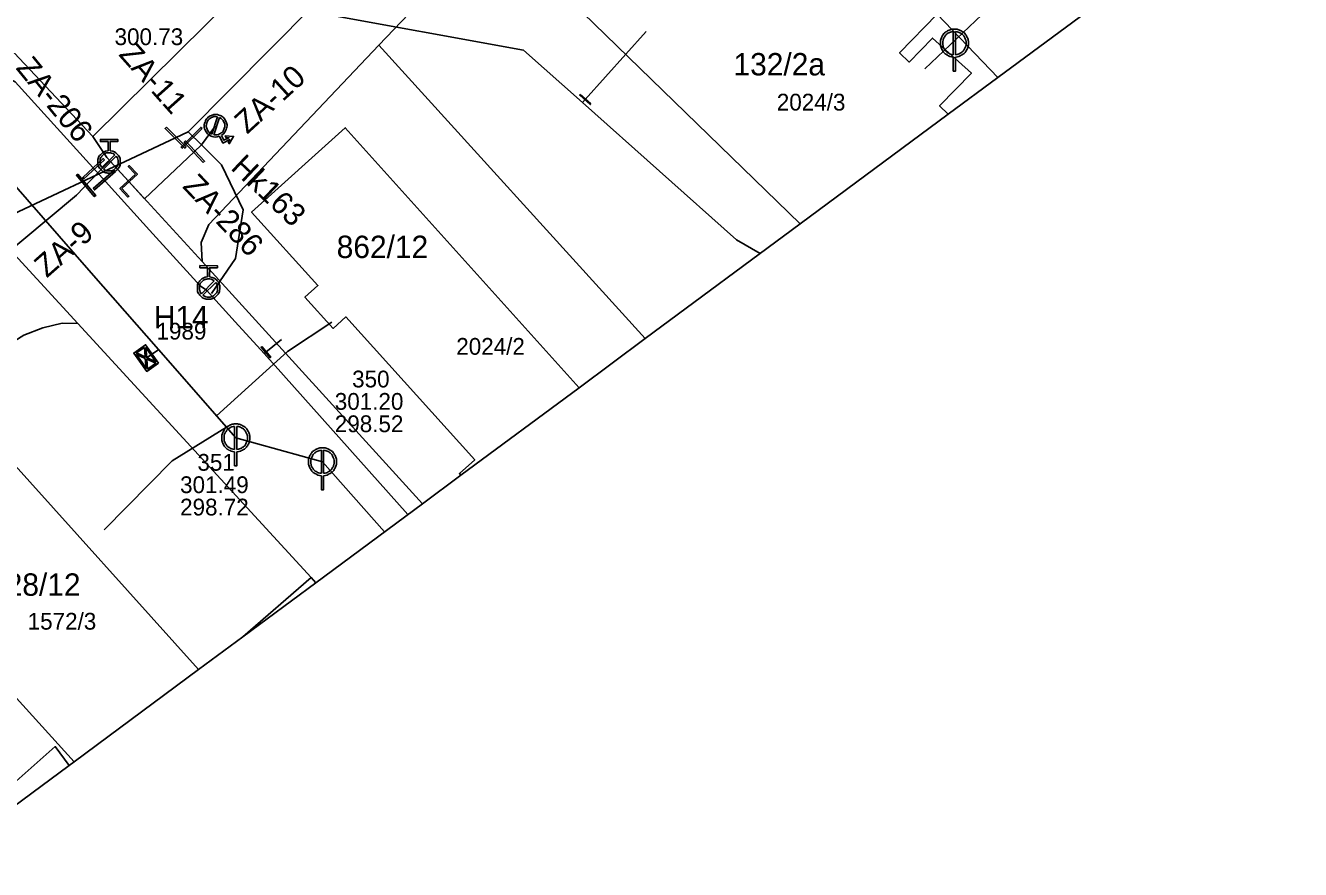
# Model space of a CAD drawing. Extents: x -570890 to -570546, y -1086481 to -1086296.
# Drawn here: x -570685 to -570571, y -1086481.2 to -1086405.7 of the extents above; entities that cross this region are included whole.
import ezdxf

# ---------------------------------------------------------------- set-up
doc = ezdxf.new("R2010")
doc.units = 0
for name, color, linetype in [('Adresní místo-text', 7, 'Continuous'), ('Armatura - popis', 7, 'Continuous'), ('Armatura vodovodní', 7, 'Continuous'), ('Default', 7, 'Continuous'), ('Dešťová vpusť', 7, 'Continuous'), ('Hydrant', 7, 'Continuous'), ('Kanalizační přípojka', 7, 'Continuous'), ('Kanalizační stoka', 7, 'Continuous'), ('Kanalizační šachta', 7, 'Continuous'), ('Označení hydrantu', 7, 'Continuous'), ('Parcela-polygon', 7, 'Continuous'), ('Parcela-text', 7, 'Continuous'), ('Popis šachty', 7, 'Continuous'), ('Vodovodní přípojka', 7, 'Continuous'), ('Vodovodní řad', 7, 'Continuous'), ('Změna materiálu', 7, 'Continuous')]:
    doc.layers.add(name, color=color, linetype=linetype)

msp = doc.modelspace()

# ---------------------------------------------------------------- linework, layer by layer
at = {"layer": 'Armatura vodovodní'}
for points in [[(-570635.43, -1086411.89), (-570634.49, -1086412.72), (-570634.54, -1086412.78), (-570635.48, -1086411.95), (-570635.43, -1086411.89)], [(-570672.44, -1086414.8), (-570670.67, -1086416.57), (-570670.78, -1086416.68), (-570672.55, -1086414.91), (-570672.44, -1086414.8)], [(-570669.25, -1086414.93), (-570671.02, -1086416.69), (-570671.13, -1086416.58), (-570669.36, -1086414.82), (-570669.25, -1086414.93)], [(-570669.14, -1086417.95), (-570670.86, -1086416.14), (-570670.74, -1086416.03), (-570669.02, -1086417.84), (-570669.14, -1086417.95)], [(-570677.98, -1086417.72), (-570679.81, -1086419.42), (-570679.91, -1086419.31), (-570678.08, -1086417.61), (-570677.98, -1086417.72)], [(-570680.36, -1086418.99), (-570678.76, -1086420.91), (-570678.88, -1086421.01), (-570680.48, -1086419.09), (-570680.36, -1086418.99)], [(-570677, -1086418.75), (-570678.87, -1086420.41), (-570678.98, -1086420.29), (-570677.1, -1086418.64), (-570677, -1086418.75)], [(-570663.91, -1086434.41), (-570663.11, -1086435.37), (-570663.17, -1086435.42), (-570663.97, -1086434.46), (-570663.91, -1086434.41)]]:
    msp.add_lwpolyline(points, dxfattribs=at)
at = {"layer": 'Default'}
for points in [[(-570602.08, -1086408.53), (-570602.34, -1086408.51), (-570602.6, -1086408.36), (-570602.9, -1086408.2), (-570603.07, -1086407.9), (-570603.23, -1086407.6), (-570603.23, -1086407.28), (-570603.23, -1086406.95), (-570603.06, -1086406.65), (-570602.89, -1086406.35), (-570602.6, -1086406.19), (-570602.3, -1086406.03), (-570601.98, -1086406.03), (-570601.67, -1086406.03), (-570601.37, -1086406.19), (-570601.07, -1086406.35), (-570600.9, -1086406.65), (-570600.73, -1086406.95), (-570600.73, -1086407.28), (-570600.73, -1086407.6), (-570600.89, -1086407.9), (-570601.06, -1086408.2), (-570601.36, -1086408.36), (-570601.62, -1086408.51), (-570601.88, -1086408.53)], [(-570602.08, -1086406.24), (-570602.28, -1086406.26), (-570602.5, -1086406.37), (-570602.74, -1086406.51), (-570602.88, -1086406.76), (-570603.02, -1086407.01), (-570603.02, -1086407.28), (-570603.02, -1086407.55), (-570602.89, -1086407.8), (-570602.75, -1086408.04), (-570602.5, -1086408.18), (-570602.29, -1086408.3), (-570602.08, -1086408.32)], [(-570601.88, -1086408.32), (-570601.67, -1086408.3), (-570601.46, -1086408.18), (-570601.21, -1086408.04), (-570601.07, -1086407.8), (-570600.94, -1086407.55), (-570600.94, -1086407.28), (-570600.94, -1086407.01), (-570601.08, -1086406.76), (-570601.22, -1086406.51), (-570601.47, -1086406.37), (-570601.68, -1086406.26), (-570601.88, -1086406.24)], [(-570667.69, -1086415.61), (-570668.01, -1086415.73), (-570668.35, -1086415.62), (-570668.74, -1086415.49), (-570668.93, -1086415.12), (-570669.12, -1086414.75), (-570668.99, -1086414.36), (-570668.88, -1086414.01), (-570668.57, -1086413.82)], [(-570667.88, -1086413.87), (-570668.15, -1086413.81), (-570668.41, -1086413.94), (-570668.71, -1086414.1), (-570668.81, -1086414.42), (-570668.92, -1086414.74), (-570668.76, -1086415.04), (-570668.63, -1086415.3), (-570668.38, -1086415.41)], [(-570668.41, -1086413.74), (-570668.07, -1086413.6), (-570667.73, -1086413.72), (-570667.33, -1086413.85), (-570667.15, -1086414.22), (-570666.96, -1086414.59), (-570667.09, -1086414.98), (-570667.2, -1086415.34), (-570667.52, -1086415.53)], [(-570668.2, -1086415.47), (-570667.93, -1086415.52), (-570667.67, -1086415.39), (-570667.37, -1086415.24), (-570667.27, -1086414.92), (-570667.16, -1086414.6), (-570667.32, -1086414.3), (-570667.45, -1086414.04), (-570667.7, -1086413.93)], [(-570677.47, -1086416.9), (-570677.11, -1086416.93), (-570676.85, -1086417.19), (-570676.56, -1086417.49), (-570676.56, -1086417.9), (-570676.56, -1086418.32), (-570676.85, -1086418.61), (-570677.15, -1086418.9), (-570677.56, -1086418.9), (-570677.97, -1086418.9), (-570678.27, -1086418.61), (-570678.56, -1086418.32), (-570678.56, -1086417.9), (-570678.56, -1086417.49), (-570678.27, -1086417.19), (-570678.01, -1086416.93), (-570677.65, -1086416.9)], [(-570677.05, -1086417.26), (-570677.27, -1086417.09), (-570677.56, -1086417.09), (-570677.9, -1086417.09), (-570678.14, -1086417.32), (-570678.37, -1086417.56), (-570678.37, -1086417.9), (-570678.37, -1086418.19), (-570678.2, -1086418.41)], [(-570678.07, -1086418.54), (-570677.85, -1086418.71), (-570677.56, -1086418.71), (-570677.23, -1086418.71), (-570676.99, -1086418.47), (-570676.75, -1086418.24), (-570676.75, -1086417.9), (-570676.75, -1086417.61), (-570676.92, -1086417.39)], [(-570668.57, -1086428.19), (-570668.21, -1086428.22), (-570667.95, -1086428.48), (-570667.66, -1086428.77), (-570667.67, -1086429.19), (-570667.67, -1086429.6), (-570667.96, -1086429.89), (-570668.26, -1086430.18), (-570668.67, -1086430.18), (-570669.08, -1086430.18), (-570669.38, -1086429.89), (-570669.67, -1086429.59), (-570669.67, -1086429.18), (-570669.66, -1086428.76), (-570669.37, -1086428.47), (-570669.11, -1086428.21), (-570668.76, -1086428.19)], [(-570668.16, -1086428.55), (-570668.37, -1086428.37), (-570668.66, -1086428.37), (-570669, -1086428.37), (-570669.24, -1086428.6), (-570669.48, -1086428.84), (-570669.48, -1086429.18), (-570669.48, -1086429.47), (-570669.31, -1086429.69)], [(-570669.17, -1086429.82), (-570668.96, -1086429.99), (-570668.67, -1086429.99), (-570668.34, -1086429.99), (-570668.1, -1086429.76), (-570667.86, -1086429.52), (-570667.86, -1086429.18), (-570667.85, -1086428.89), (-570668.03, -1086428.68)], [(-570666.34, -1086443.83), (-570666.59, -1086443.81), (-570666.86, -1086443.67), (-570667.15, -1086443.5), (-570667.32, -1086443.21), (-570667.48, -1086442.91), (-570667.48, -1086442.58), (-570667.48, -1086442.26), (-570667.31, -1086441.96), (-570667.15, -1086441.66), (-570666.85, -1086441.49), (-570666.55, -1086441.33), (-570666.23, -1086441.33), (-570665.92, -1086441.33), (-570665.62, -1086441.49), (-570665.32, -1086441.66), (-570665.15, -1086441.96), (-570664.98, -1086442.26), (-570664.98, -1086442.58), (-570664.98, -1086442.91), (-570665.15, -1086443.21), (-570665.31, -1086443.5), (-570665.61, -1086443.67), (-570665.87, -1086443.81), (-570666.13, -1086443.83)], [(-570666.34, -1086441.55), (-570666.53, -1086441.56), (-570666.75, -1086441.68), (-570667, -1086441.81), (-570667.14, -1086442.06), (-570667.28, -1086442.31), (-570667.28, -1086442.58), (-570667.28, -1086442.85), (-570667.14, -1086443.1), (-570667, -1086443.35), (-570666.75, -1086443.48), (-570666.54, -1086443.6), (-570666.34, -1086443.62)], [(-570666.13, -1086443.62), (-570665.93, -1086443.6), (-570665.71, -1086443.48), (-570665.46, -1086443.35), (-570665.33, -1086443.1), (-570665.19, -1086442.85), (-570665.19, -1086442.58), (-570665.19, -1086442.31), (-570665.33, -1086442.06), (-570665.47, -1086441.81), (-570665.72, -1086441.68), (-570665.93, -1086441.56), (-570666.13, -1086441.55)], [(-570658.58, -1086445.97), (-570658.84, -1086445.95), (-570659.1, -1086445.8), (-570659.4, -1086445.64), (-570659.56, -1086445.34), (-570659.73, -1086445.04), (-570659.73, -1086444.72), (-570659.73, -1086444.39), (-570659.56, -1086444.09), (-570659.39, -1086443.79), (-570659.09, -1086443.63), (-570658.8, -1086443.47), (-570658.48, -1086443.47), (-570658.16, -1086443.47), (-570657.87, -1086443.63), (-570657.57, -1086443.79), (-570657.4, -1086444.09), (-570657.23, -1086444.39), (-570657.23, -1086444.72), (-570657.23, -1086445.04), (-570657.39, -1086445.34), (-570657.56, -1086445.64), (-570657.86, -1086445.8), (-570658.12, -1086445.95), (-570658.38, -1086445.97)], [(-570658.58, -1086443.68), (-570658.78, -1086443.7), (-570658.99, -1086443.81), (-570659.24, -1086443.95), (-570659.38, -1086444.2), (-570659.52, -1086444.45), (-570659.52, -1086444.72), (-570659.52, -1086444.99), (-570659.39, -1086445.24), (-570659.25, -1086445.48), (-570659, -1086445.62), (-570658.79, -1086445.74), (-570658.58, -1086445.75)], [(-570658.38, -1086445.75), (-570658.17, -1086445.74), (-570657.96, -1086445.62), (-570657.71, -1086445.48), (-570657.57, -1086445.24), (-570657.44, -1086444.99), (-570657.44, -1086444.72), (-570657.44, -1086444.45), (-570657.58, -1086444.2), (-570657.72, -1086443.95), (-570657.97, -1086443.81), (-570658.18, -1086443.7), (-570658.38, -1086443.68)]]:
    msp.add_open_spline(points, degree=3, dxfattribs=at)
at = {"layer": 'Dešťová vpusť'}
for points in [[(-570673.15, -1086435.9), (-570674.2, -1086436.64), (-570675.35, -1086435), (-570674.29, -1086434.26), (-570673.15, -1086435.9)], [(-570674.39, -1086434.49), (-570675.11, -1086434.98), (-570674.33, -1086435.34), (-570674.39, -1086434.49)], [(-570674.2, -1086435.4), (-570673.39, -1086435.77), (-570674.27, -1086434.51), (-570674.2, -1086435.4)], [(-570674.32, -1086435.48), (-570675.11, -1086435.12), (-570674.25, -1086436.35), (-570674.32, -1086435.48)], [(-570674.19, -1086435.54), (-570674.12, -1086436.43), (-570673.38, -1086435.91), (-570674.19, -1086435.54)]]:
    msp.add_lwpolyline(points, dxfattribs=at)
at = {"layer": 'Hydrant'}
for points in [[(-570668.57, -1086413.82), (-570668.41, -1086413.74)], [(-570668.38, -1086415.41), (-570667.88, -1086413.87)], [(-570667.7, -1086413.93), (-570668.2, -1086415.47)], [(-570667.52, -1086415.53), (-570667.3, -1086415.97), (-570666.85, -1086415.74), (-570667.1, -1086415.73), (-570667.18, -1086415.57), (-570666.43, -1086415.63), (-570666.82, -1086416.28), (-570666.9, -1086416.11), (-570666.77, -1086415.91), (-570667.38, -1086416.22), (-570667.69, -1086415.61)], [(-570677.65, -1086416.9), (-570677.65, -1086416.09), (-570678.34, -1086416.09), (-570678.34, -1086415.9), (-570676.78, -1086415.9), (-570676.78, -1086416.09), (-570677.47, -1086416.09), (-570677.47, -1086416.9)], [(-570678.2, -1086418.41), (-570677.05, -1086417.26)], [(-570676.92, -1086417.39), (-570678.07, -1086418.54)], [(-570668.76, -1086428.19), (-570668.75, -1086427.37), (-570669.44, -1086427.37), (-570669.44, -1086427.18), (-570667.88, -1086427.19), (-570667.88, -1086427.37), (-570668.56, -1086427.37), (-570668.57, -1086428.19)], [(-570669.31, -1086429.69), (-570668.16, -1086428.55)], [(-570668.03, -1086428.68), (-570669.17, -1086429.82)]]:
    msp.add_lwpolyline(points, dxfattribs=at)
at = {"layer": 'Kanalizační přípojka'}
for p, q in [((-570604.63, -1086409.59), (-570594.43, -1086399.88)), ((-570657.65, -1086432.23), (-570661.62, -1086434.87)), ((-570671.92, -1086444.63), (-570667.07, -1086441.63)), ((-570677.99, -1086450.8), (-570671.92, -1086444.63))]:
    msp.add_line(p, q, dxfattribs=at)
for points in [[(-570674.25, -1086435.45), (-570673.12, -1086434.67)], [(-570661.62, -1086434.87), (-570667.95, -1086440.62)]]:
    msp.add_lwpolyline(points, dxfattribs=at)
at = {"layer": 'Kanalizační stoka'}
for points in [[(-570692.07, -1086413.07), (-570679.15, -1086427.82), (-570673.15, -1086434.69), (-570666.23, -1086442.58)], [(-570666.23, -1086442.58), (-570658.48, -1086444.72)], [(-570658.48, -1086444.72), (-570652.93, -1086450.98)]]:
    msp.add_lwpolyline(points, dxfattribs=at)
at = {"layer": 'Kanalizační šachta'}
for points in [[(-570602.08, -1086408.32), (-570602.08, -1086406.24)], [(-570601.88, -1086406.24), (-570601.88, -1086408.32)], [(-570601.88, -1086408.53), (-570601.88, -1086409.78), (-570602.08, -1086409.78), (-570602.08, -1086408.53)], [(-570666.34, -1086443.62), (-570666.34, -1086441.55)], [(-570666.13, -1086441.55), (-570666.13, -1086443.62)], [(-570666.13, -1086443.83), (-570666.13, -1086445.08), (-570666.34, -1086445.08), (-570666.34, -1086443.83)], [(-570658.58, -1086445.75), (-570658.58, -1086443.68)], [(-570658.38, -1086443.68), (-570658.38, -1086445.75)], [(-570658.38, -1086445.97), (-570658.38, -1086447.22), (-570658.58, -1086447.22), (-570658.58, -1086445.97)]]:
    msp.add_lwpolyline(points, dxfattribs=at)
at = {"layer": 'Parcela-polygon'}
for p, q in [((-570598.1, -1086410.36), (-570585.58, -1086401.09)), ((-570602.53, -1086413.64), (-570598.1, -1086410.36)), ((-570615.76, -1086423.44), (-570602.53, -1086413.64)), ((-570629.62, -1086433.71), (-570615.76, -1086423.44)), ((-570635.54, -1086438.1), (-570629.62, -1086433.71)), ((-570646.1, -1086445.92), (-570635.54, -1086438.1)), ((-570649.55, -1086448.48), (-570646.1, -1086445.92)), ((-570659.07, -1086455.53), (-570649.55, -1086448.48)), ((-570665.6, -1086460.37), (-570659.07, -1086455.53)), ((-570669.56, -1086463.3), (-570665.6, -1086460.37)), ((-570680.68, -1086471.54), (-570669.56, -1086463.3)), ((-570681.14, -1086471.88), (-570680.68, -1086471.54))]:
    msp.add_line(p, q, dxfattribs=at)
for points in [[(-570583.23, -1086320.67), (-570596.46, -1086333.85), (-570601.07, -1086338.45), (-570622.35, -1086359.65), (-570651.08, -1086388.01), (-570679.02, -1086415.64), (-570677.75, -1086417.52), (-570669.23, -1086426.82), (-570669.33, -1086425.11), (-570668.65, -1086423.5), (-570653.44, -1086407.45), (-570627.97, -1086380.81), (-570613.03, -1086365.73), (-570583.9, -1086336.34), (-570582.04, -1086334.46), (-570579.74, -1086332.2), (-570577.95, -1086330.46), (-570571.04, -1086323.78)], [(-570585.58, -1086401.09), (-570586.81, -1086399.86), (-570588.49, -1086398.17), (-570590.24, -1086396.42), (-570597.85, -1086388.71), (-570598.1, -1086388.36), (-570608.15, -1086378.61), (-570608.49, -1086378.23), (-570610.73, -1086375.72), (-570612.02, -1086373.78), (-570612.8, -1086370.23), (-570613.03, -1086365.73), (-570627.97, -1086380.81), (-570619.89, -1086389.23), (-570611.49, -1086396.95), (-570603.52, -1086404.68), (-570598.1, -1086410.36)], [(-570615.76, -1086423.44), (-570636.25, -1086403.55), (-570626.03, -1086392.93), (-570616.53, -1086402.15), (-570611.49, -1086396.95), (-570619.89, -1086389.23), (-570627.97, -1086380.81), (-570653.44, -1086407.45), (-570629.62, -1086433.71)], [(-570602.53, -1086413.64), (-570603.3, -1086412.89), (-570600.46, -1086409.96), (-570603.93, -1086406.83), (-570606.02, -1086408.98), (-570606.88, -1086408.15), (-570603.52, -1086404.68), (-570611.49, -1086396.95), (-570616.53, -1086402.15), (-570626.03, -1086392.93), (-570636.25, -1086403.55), (-570615.76, -1086423.44)], [(-570649.55, -1086448.48), (-570669.23, -1086426.82), (-570677.75, -1086417.52), (-570679.02, -1086415.64), (-570699.23, -1086394.15)], [(-570598.1, -1086410.36), (-570603.52, -1086404.68), (-570606.88, -1086408.15), (-570606.02, -1086408.98), (-570603.93, -1086406.83), (-570600.46, -1086409.96), (-570603.3, -1086412.89), (-570602.53, -1086413.64)], [(-570629.62, -1086433.71), (-570653.44, -1086407.45), (-570668.65, -1086423.5), (-570669.33, -1086425.11), (-570669.23, -1086426.82), (-570649.55, -1086448.48)], [(-570635.54, -1086438.1), (-570656.45, -1086414.85), (-570664.82, -1086422.4), (-570658.89, -1086428.97), (-570660.05, -1086430.01), (-570657.54, -1086432.79), (-570656.38, -1086431.76), (-570644.86, -1086444.54), (-570646.23, -1086445.78), (-570646.1, -1086445.92)], [(-570646.1, -1086445.92), (-570646.23, -1086445.78), (-570644.86, -1086444.54), (-570656.38, -1086431.76), (-570657.54, -1086432.79), (-570660.05, -1086430.01), (-570658.89, -1086428.97), (-570664.82, -1086422.4), (-570656.45, -1086414.85), (-570635.54, -1086438.1)], [(-570726.86, -1086470.29), (-570720.84, -1086464.38), (-570716.94, -1086468.7), (-570700.75, -1086452.36), (-570702.17, -1086447.55), (-570695.62, -1086441.51), (-570687.38, -1086434.77), (-570685.19, -1086433.4), (-570683.47, -1086432.73), (-570681.75, -1086432.33), (-570680.36, -1086432.34), (-570685.68, -1086426.55), (-570687.54, -1086424.56), (-570687.78, -1086425.47), (-570688.21, -1086426.47), (-570688.87, -1086427.37), (-570714.36, -1086450.68), (-570730.58, -1086466.4), (-570732.62, -1086468.39)], [(-570685.68, -1086426.55), (-570680.36, -1086432.34), (-570659.48, -1086455.08), (-570659.07, -1086455.53)], [(-570665.6, -1086460.37), (-570659.48, -1086455.08), (-570680.36, -1086432.34), (-570681.75, -1086432.33), (-570683.47, -1086432.73), (-570685.19, -1086433.4), (-570687.38, -1086434.77), (-570695.62, -1086441.51), (-570702.17, -1086447.55), (-570700.75, -1086452.36), (-570716.94, -1086468.7), (-570720.84, -1086464.38), (-570726.86, -1086470.29)], [(-570680.68, -1086471.54), (-570697.04, -1086453.52), (-570686.77, -1086444.17), (-570669.56, -1086463.3)], [(-570669.56, -1086463.3), (-570686.77, -1086444.17), (-570697.04, -1086453.52), (-570680.68, -1086471.54)], [(-570659.07, -1086455.53), (-570659.48, -1086455.08), (-570665.6, -1086460.37)], [(-570694.48, -1086480.92), (-570682.38, -1086470.18), (-570681.14, -1086471.88)], [(-570681.14, -1086471.88), (-570682.38, -1086470.18), (-570694.48, -1086480.92)], [(-570694.48, -1086480.92), (-570693.7, -1086481.18), (-570681.14, -1086471.88)]]:
    msp.add_lwpolyline(points, dxfattribs=at)
msp.add_lwpolyline([(-570651.08, -1086388.01), (-570672.28, -1086366.53), (-570677.97, -1086372.52), (-570699.23, -1086394.15), (-570679.02, -1086415.64)], close=True, dxfattribs=at)
at = {"layer": 'Vodovodní přípojka'}
msp.add_line((-570662.14, -1086433.77), (-570663.69, -1086435.04), dxfattribs=at)
msp.add_lwpolyline([(-570635.23, -1086412.6), (-570634.99, -1086412.33), (-570629.55, -1086406.23)], dxfattribs=at)
at = {"layer": 'Vodovodní řad'}
msp.add_line((-570668.04, -1086414.67), (-570669.3, -1086416.39), dxfattribs=at)
for points in [[(-570678.46, -1086419.03), (-570685.95, -1086410.73), (-570689.67, -1086408.92), (-570699.18, -1086398.29), (-570708.68, -1086387.67), (-570715.69, -1086380.26)], [(-570659.39, -1086404.05), (-570670.5, -1086415.21)], [(-570658.91, -1086404.56), (-570640.51, -1086407.9), (-570635.23, -1086412.6), (-570621.47, -1086424.86), (-570619.35, -1086426.1)], [(-570671.61, -1086415.74), (-570670.5, -1086415.21), (-570669.3, -1086416.39)], [(-570671.61, -1086415.74), (-570690.15, -1086424.46), (-570693.01, -1086425.97), (-570699.4, -1086431.61), (-570708.97, -1086440.64), (-570710.52, -1086442.29), (-570713.79, -1086445.84), (-570732.6, -1086462.86), (-570736.53, -1086467.11)], [(-570669.3, -1086416.39), (-570669.94, -1086416.99), (-570674.38, -1086421.2), (-570675.81, -1086419.64)], [(-570669.3, -1086416.39), (-570667.51, -1086418.16), (-570665.58, -1086422.2), (-570666.27, -1086426.54), (-570668.4, -1086429.66)], [(-570678.52, -1086418.82), (-570677.54, -1086417.86)], [(-570675.81, -1086419.64), (-570677.48, -1086417.8)], [(-570694.81, -1086432.82), (-570680.46, -1086420.88), (-570678.52, -1086418.82)], [(-570650.86, -1086449.44), (-570663.69, -1086435.04), (-570666.28, -1086432.21), (-570668.86, -1086429.38), (-570669.43, -1086428.98), (-570673.95, -1086424.01), (-570678.46, -1086419.03)]]:
    msp.add_lwpolyline(points, dxfattribs=at)
at = {"layer": 'Změna materiálu'}
msp.add_lwpolyline([(-570675.21, -1086419), (-570675.84, -1086418.31), (-570675.75, -1086418.23), (-570675.03, -1086419.01), (-570676.41, -1086420.27), (-570675.78, -1086420.97), (-570675.87, -1086421.05), (-570676.59, -1086420.27), (-570675.21, -1086419)], dxfattribs=at)

# ---------------------------------------------------------------- texts
at = {"layer": 'Adresní místo-text'}
for s, p in [('132/2a', (-570621.73, -1086410.17)), ('862/12', (-570657.21, -1086426.5)), ('228/12', (-570688.29, -1086456.7))]:
    msp.add_text(s, height=2, dxfattribs=at).set_placement(p)
at = {"layer": 'Armatura - popis'}
for s, rotation, p in [('ZA-11', 311.7382, (-570676.77, -1086408.34)), ('ZA-206', 309.2538, (-570685.96, -1086409.53)), ('ZA-10', 42.4908, (-570665.21, -1086415.47)), ('ZA-286', 313.4751, (-570671.07, -1086420.15)), ('ZA-9', 41.5009, (-570683.13, -1086428.33))]:
    msp.add_text(s, height=2, rotation=rotation, dxfattribs=at).set_placement(p)
at = {"layer": 'Označení hydrantu'}
msp.add_text('Hk163', height=2, rotation=316.6685, dxfattribs=at).set_placement((-570666.77, -1086418.51))
msp.add_text('H14', height=2, dxfattribs=at).set_placement((-570673.56, -1086432.78))
at = {"layer": 'Parcela-text'}
for s, p in [('2024/3', (-570617.86, -1086413.31)), ('1989', (-570673.32, -1086433.79)), ('2024/2', (-570646.52, -1086435.15)), ('1572/3', (-570684.84, -1086459.73))]:
    msp.add_text(s, height=1.5, dxfattribs=at).set_placement(p)
at = {"layer": 'Popis šachty'}
for s, p in [('300.73', (-570677.07, -1086407.46)), ('350', (-570655.83, -1086438.07)), ('301.20', (-570657.38, -1086440.07)), ('298.52', (-570657.38, -1086442.07)), ('351', (-570669.66, -1086445.52)), ('301.49', (-570671.21, -1086447.52)), ('298.72', (-570671.21, -1086449.52))]:
    msp.add_text(s, height=1.5, dxfattribs=at).set_placement(p)

doc.saveas('drawing.dxf')
